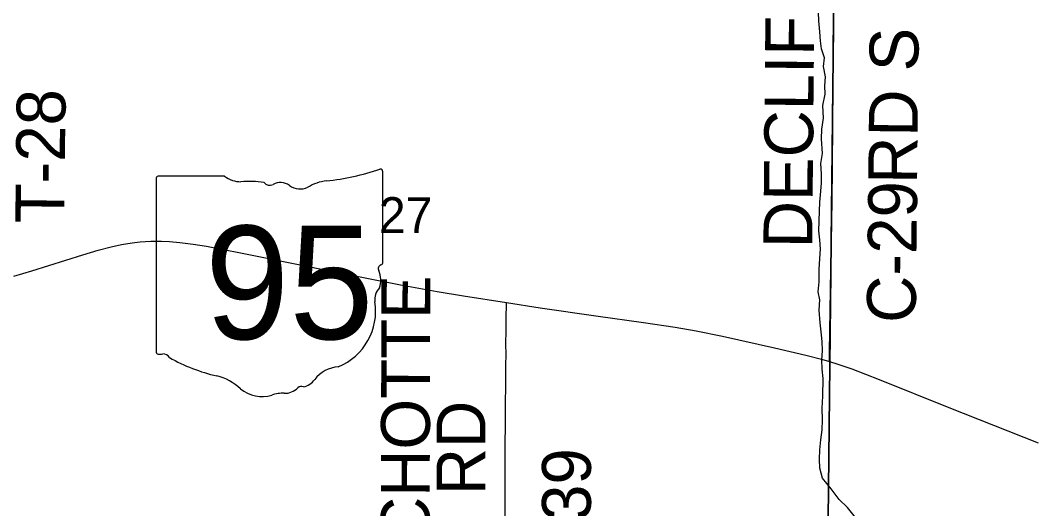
# Model space of a CAD drawing. Extents: x 1584893 to 1934202, y 663575 to 1091909.
# Drawn here: x 1729310 to 1735520, y 938992 to 941991 of the extents above; entities that cross this region are included whole.
import ezdxf

# ---------------------------------------------------------------- set-up
doc = ezdxf.new("R2010")
doc.units = 0
for name, color, linetype in [('GM_X_County_Road', 7, 'Continuous'), ('GM_X_County_Road_Text', 7, 'Continuous'), ('GM_X_Minor_River', 7, 'Continuous'), ('GM_X_Section', 7, 'Continuous'), ('GM_X_Section_Text', 7, 'Continuous'), ('GM_X_State_Location', 7, 'Continuous'), ('GM_X_State_Route', 7, 'Continuous'), ('GM_X_State_Shield', 7, 'Continuous'), ('GM_X_Township_Road', 7, 'Continuous'), ('GM_X_Township_Road_Text', 7, 'Continuous')]:
    doc.layers.add(name, color=color, linetype=linetype)

msp = doc.modelspace()

# ---------------------------------------------------------------- linework, layer by layer
at = {"layer": 'GM_X_County_Road'}
msp.add_lwpolyline([(1734278.2, 939895.5), (1734278.7, 939953.1), (1734279.9, 940084.1), (1734286.5, 940460.7), (1734292.5, 940739), (1734297.1, 941066.4), (1734299.9, 941377.3), (1734301.5, 941557.4), (1734302.8, 942245.2), (1734304.6, 942507.2), (1734304.3, 942736.5), (1734306.1, 942883.8), (1734306, 942928.9)], dxfattribs=at)
at = {"layer": 'GM_X_Minor_River'}
msp.add_lwpolyline([(1734437.7, 938937.5), (1734388.6, 939000.5), (1734337.4, 939049.4), (1734288.4, 939114.4), (1734235.4, 939179.4), (1734218.4, 939241.9), (1734217.3, 939296), (1734220.2, 939354.1), (1734225.2, 939414.2), (1734234.2, 939476.2), (1734235.2, 939538.3), (1734234.4, 939610.5), (1734237.6, 939682.6), (1734239.4, 939790.8), (1734234.3, 939849.1), (1734231.3, 939907.2), (1734236.1, 939961.3), (1734233.1, 940019.5), (1734228, 940077.7), (1734221, 940133.9), (1734216.2, 940212.2), (1734219.2, 940274.3), (1734208.1, 940324.6), (1734215, 940384.6), (1734214.3, 940462.8), (1734219.4, 940526.9), (1734224.4, 940587), (1734219.3, 940643.2), (1734212.2, 940699.4), (1734218.2, 940819.6), (1734219.1, 940873.7), (1734226.2, 940941.8), (1734229, 940993.8), (1734229.9, 941047.9), (1734225, 941112.2), (1734236, 941174.1), (1734229.4, 941262.5), (1734232.4, 941322.5), (1734241.5, 941390.5), (1734236.8, 941468.8), (1734252, 941536.7), (1734250.8, 941588.9), (1734253.7, 941644.9), (1734242.7, 941707.3), (1734247.6, 941761.3), (1734230.5, 941815.7), (1734223.3, 941865.9), (1734220.2, 941920.1), (1734213.3, 941988.4), (1734212.1, 942038.5)], dxfattribs=at)
at = {"layer": 'GM_X_Section'}
msp.add_lwpolyline([(1734314.2, 942895.5), (1734256.8, 937607.5)], dxfattribs=at)
msp.add_lwpolyline([(1734314.2, 942895.5), (1739520.5, 942867.1), (1739430.9, 937549.2), (1734256.8, 937607.5)], close=True, dxfattribs=at)
at = {"layer": 'GM_X_State_Route'}
msp.add_lwpolyline([(1729272, 940420.2), (1729382.6, 940452.1), (1729695.5, 940551.7), (1729789.8, 940579.7), (1729869, 940600.3), (1729933, 940614.1), (1729997.5, 940624.8), (1730046.1, 940630.3), (1730111.4, 940634.1), (1730176.8, 940634.4), (1730225.8, 940632.5), (1730291.1, 940627.3), (1730372.3, 940617.2), (1730453.1, 940604), (1730662.5, 940563.2), (1730734.5, 940548.8), (1731241.9, 940447.1), (1731644.3, 940366.3), (1731870.4, 940324.9), (1732032.5, 940298.7), (1732296.6, 940257.8), (1732503, 940225.8), (1732844.3, 940177.4), (1733136.9, 940136.3), (1733331.6, 940107.3), (1733460.9, 940084.8), (1733621.5, 940051.6), (1733941.9, 939980.2), (1734133.6, 939935.4), (1734228.7, 939910.3), (1734278.2, 939895.5), (1734322.8, 939882), (1734415.9, 939850.4), (1734584, 939784.9), (1735010.8, 939614.5), (1735560, 939396.4)], dxfattribs=at)
at = {"layer": 'GM_X_State_Shield'}
for p, q in [((1730565.4, 941033.7), (1730157.7, 941033.7)), ((1731536.2, 940507.2), (1731536.2, 941059.9)), ((1730144, 941015.5), (1730144, 939958.9)), ((1731536, 940507.3), (1731536.2, 940507.2))]:
    msp.add_line(p, q, dxfattribs=at)
for centre, radius, start, end in [((1730160, 941017.8), 16.1, 98.1301, 188.1301), ((1730662.5, 941156.4), 156.4, 231.61951, 271.11188), ((1731040.3, 942474.3), 1476.4, 275.84447, 288.90645), ((1731520.7, 941062.2), 15.5, 351.86209, 97.738), ((1730714.4, 940440.5), 561.6, 80.48669, 94.98827), ((1730841.9, 941023.3), 45.1, 219.79206, 297.10237), ((1730908.1, 940901.1), 93.8, 54.46668, 119.14113), ((1731029.2, 941068.6), 112.9, 233.85621, 294.82819), ((1731228.6, 940711), 297, 97.34618, 120.76885), ((1731532.6, 940466.6), 24, 107.94398, 210.33697), ((1731519.6, 940505), 16.6, 289.60381, 7.73413), ((1731380, 940396.7), 144, 340.03296, 23.64957), ((1731591.7, 940275.8), 104.8, 136.8065, 186.92959), ((1731123, 940205.5), 369.3, 292.30889, 8.98584), ((1730160.1, 939956.6), 16.3, 171.95839, 258.30661), ((1730162.6, 940064.7), 124.2, 267.33899, 280.60386), ((1730188, 939897.9), 44.8, 29.74838, 93.27175), ((1730753.3, 940847.3), 1066.1, 240.41292, 257.1985), ((1731278.7, 939662.3), 202.2, 94.40312, 142.57675), ((1730435.4, 939484.2), 333.6, 47.18416, 75.83597), ((1731022.4, 939856.5), 119.3, 282.87319, 323.27711), ((1730796.2, 939892.7), 211.7, 230.70037, 286.29184), ((1730934, 939813.6), 112.8, 268.77702, 315.54927), ((1731036, 939711.2), 31.8, 65.75173, 132.64842), ((1730918.5, 939527.4), 173.9, 85.69512, 111.20995)]:
    msp.add_arc(centre, radius, start, end, dxfattribs=at)
at = {"layer": 'GM_X_Township_Road'}
msp.add_lwpolyline([(1732287.6, 938846.4), (1732287.8, 939010.9), (1732287.4, 939125.9), (1732287.3, 939224.6), (1732288.2, 939356.1), (1732290.1, 939537), (1732290.3, 939602.7), (1732290.2, 939668.4), (1732290.8, 939717.6), (1732290.7, 939750.5), (1732290.9, 939783.3), (1732290.9, 939849), (1732291.5, 939865.4), (1732292.1, 939898.3), (1732292.8, 939914.7), (1732293.3, 939931.1), (1732293.4, 939947.6), (1732292.4, 939996.7), (1732293.2, 940095.4), (1732294.1, 940177.5), (1732295.9, 940236.6), (1732296.6, 940257.8)], dxfattribs=at)

# ---------------------------------------------------------------- texts
at = {"layer": 'GM_X_County_Road_Text'}
for s, rotation, p in [('DECLIFF', 89.49375, (1734172.5, 940590.6)), ('RD S', 89.37528, (1734816.2, 940985.2)), ('C-29', 89.32056, (1734807.4, 940131.7))]:
    msp.add_text(s, height=300, rotation=rotation, dxfattribs=at).set_placement(p)
at = {"layer": 'GM_X_Section_Text'}
msp.add_text('27', height=221, rotation=0.00001, dxfattribs=at).set_placement((1731512, 940684.1))
at = {"layer": 'GM_X_State_Location'}
for s in ['s', 'r']:
    msp.add_text(s, height=1, dxfattribs=at).set_placement((1730824.4, 940417))
msp.add_text('95', height=1, rotation=0.00001, dxfattribs=at).set_placement((1730572.6, 940344.2))
at = {"layer": 'GM_X_State_Shield'}
msp.add_text('95', height=696.1, dxfattribs=at).set_placement((1730444.4, 940033.4))
at = {"layer": 'GM_X_Township_Road_Text'}
for s, rotation, p in [('T-28', 89.30252, (1729579.7, 940742.3)), ('SCHOTTE', 89.84716, (1731822.9, 938507.7)), ('RD', 90, (1732166.3, 939075.5)), ('T-39', 90, (1732813.7, 938538.7))]:
    msp.add_text(s, height=300, rotation=rotation, dxfattribs=at).set_placement(p)

doc.saveas('drawing.dxf')
